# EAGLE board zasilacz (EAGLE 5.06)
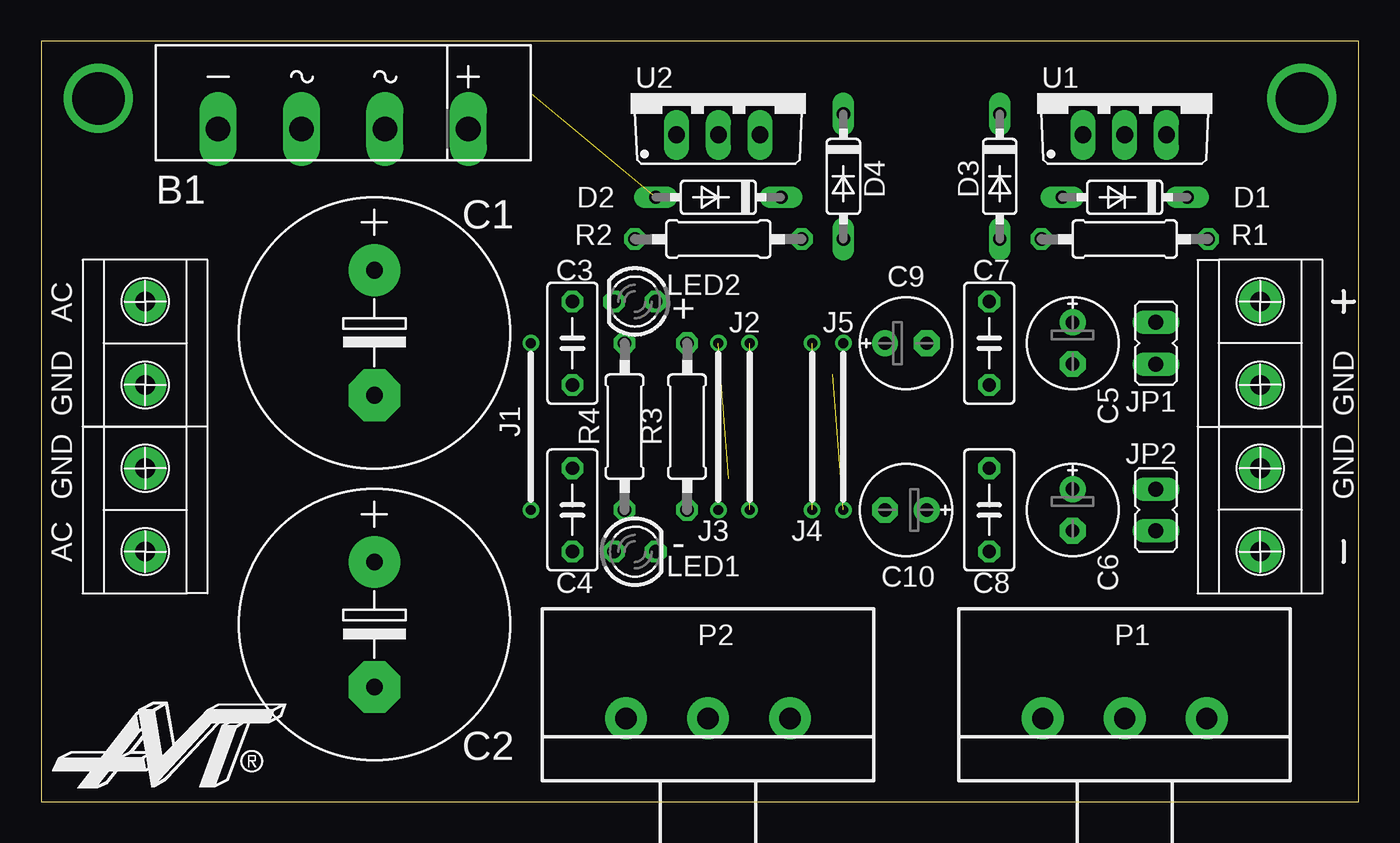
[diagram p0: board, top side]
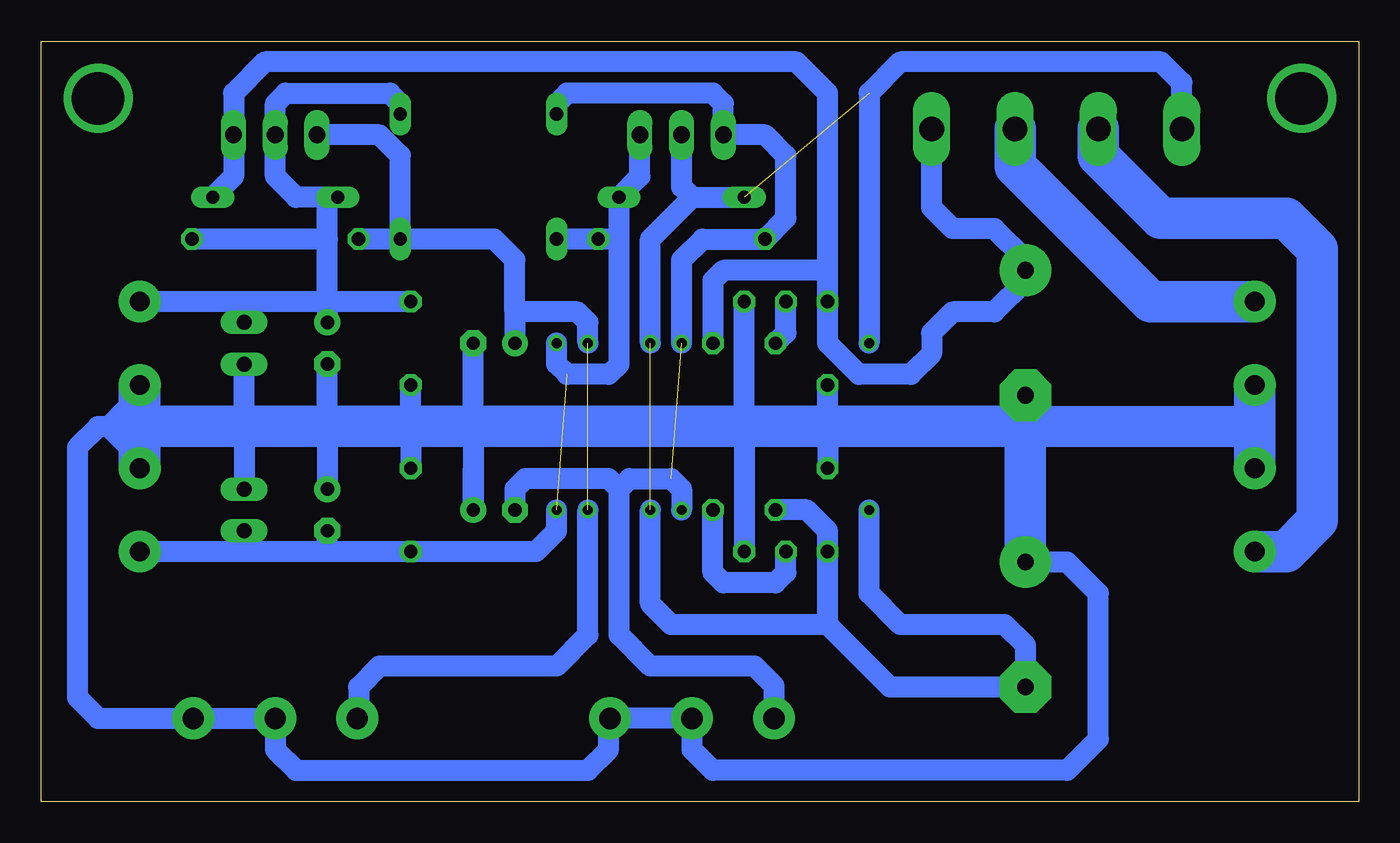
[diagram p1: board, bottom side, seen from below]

Size 80.32 x 46.34 mm. Coordinates in mm from the lower left corner, seen from the top.
Outline: 0,0 80.32,0 80.32,46.34 0,46.34 0,0
Copper layers (1*16): Top 0.035mm / dielectric 1.5mm / Bottom 0.035mm
Design rules "default": minimum track width 10mil, minimum drill 24mil, track to track 8mil, track to pad 8mil, pad to pad 8mil, via to via 8mil, smd to smd 8mil, copper to edge 40mil, drill to drill 8mil, minimum pad ring 10mil, minimum via ring 8mil, stop-mask expansion 4mil, vias tented up to drill 0mil, thermal gap 10mil

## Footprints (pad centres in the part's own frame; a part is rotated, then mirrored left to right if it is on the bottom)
FBU4 = drill 1.499 long: + 7.62,-1.54; - -7.62,-1.54; AC1 2.54,-1.54; AC2 -2.54,-1.54
E7,5-16 = drill 1.016 pad 3.15 round: + -3.81,0 | drill 1.016 pad 3.15 octagon: - 3.81,0
C050-030X075 = drill 0.813 octagon: 1 -2.54,0; 2 2.54,0
E2,5-6E = drill 0.813 pad 1.575 round: + -1.27,0 | drill 0.813 pad 1.575 octagon: - 1.27,0
DO35-7 = drill 0.813 long: A 3.81,0; C -3.81,0
JP1 = drill 0.914 long: 1 0,-1.27; 2 0,1.27
LED3MM = drill 0.813 octagon: A -1.27,0; K 1.27,0
CIP20C-4MM = drill 1.3 pad 2.54 round: A -5,0; E 5,0; S 0,0
0207/10 = drill 0.813 octagon: 1 -5.08,0; 2 5.08,0
TO220BV = drill 1.016 long: D 0,-2.54; G -2.54,-2.54; S 2.54,-2.54
ARK2 = drill 1.2 pad 2.54 round: 1 -2.54,0; 3 2.54,0 | drill 0.8 pad 2.54 round: 2 2.54,0

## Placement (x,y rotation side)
B1  RECTIFIER-FBU4  [FBU4]  18.42,42.55 0 top
C1  [E7,5-16]  20.32,28.58 270 top
C2  [E7,5-16]  20.32,10.79 270 top
C3  [C050-030X075]  32.38,27.94 270 top
C4  [C050-030X075]  32.38,17.78 270 top
C5  [E2,5-6E]  62.86,27.94 270 top
C6  [E2,5-6E]  62.86,17.78 270 top
C7  [C050-030X075]  57.78,27.94 270 top
C8  [C050-030X075]  57.78,17.78 270 top
C9  [E2,5-6E]  52.7,27.94 0 top
C10  [E2,5-6E]  52.7,17.78 180 top
D1  1N4007  [DO35-7]  66.04,36.83 180 top
D2  1N4007  [DO35-7]  41.27,36.83 180 top
D3  1N4007  [DO35-7]  58.42,38.1 270 top
D4  1N4007  [DO35-7]  48.89,38.1 270 top
JP1  [JP1]  67.95,27.94 0 top
JP2  [JP1]  67.95,17.78 0 top
LED1  [LED3MM]  36.2,15.24 0 top
LED2  [LED3MM]  36.2,30.48 180 top
P1  [CIP20C-4MM]  66.04,5.08 0 top
P2  [CIP20C-4MM]  40.64,5.08 0 top
R1  [0207/10]  66.04,34.29 0 top
R2  [0207/10]  41.27,34.29 180 top
R3  [0207/10]  39.37,22.86 90 top
R4  [0207/10]  35.56,22.86 90 top
U1  LM317  [TO220BV]  66.04,43.18 0 top
U2  LM337  [TO220BV]  41.27,43.18 0 top
U$1  ARK2  [ARK2]  6.35,27.94 270 top
U$2  ARK2  [ARK2]  6.35,17.78 270 top
U$3  ARK2  [ARK2]  74.3,27.94 90 top
U$4  ARK2  [ARK2]  74.3,17.78 90 top

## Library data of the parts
B1 = rectifier
C1-C10 R1-R4 = rcl
D1-D4 = diode
JP1 JP2 = jumper
LED1 LED2 = led
P1 P2 = pot2
U1 U2 = transistor-power
U$1-U$4 = ark2

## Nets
N$1: B1.AC1 U$1.1
N$2: B1.AC2 U$2.2
N$4: B1.- C2.- C4.2 D2.A R4.1 U2.D
N$5: C5.+ C7.1 D1.A D3.C JP1.2 R1.2 U1.D U$3.2
N$6: C6.- C8.2 D2.C D4.A JP2.1 R2.1 U2.S U$4.1
N$7: C9.+ D3.A P1.A R1.1 U1.G
N$8: C10.- D4.C P2.A R2.2 U2.G
N$9: LED1.A R3.1
N$10: LED2.K R4.2
N$11: C1.- C2.+ C3.2 C4.1 C5.- C6.+ C7.2 C8.1 C9.- C10.+ JP1.1 JP2.2 LED1.K LED2.A P1.E P1.S P2.E P2.S U$1.2 U$2.1 U$3.1 U$4.2
N$14: B1.+ C1.+ C3.1 D1.C R3.2 U1.S

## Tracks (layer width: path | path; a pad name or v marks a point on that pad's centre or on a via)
N$1
  Bottom 2.54: U$1.1 12.7,30.48 20.96,38.73 B1.AC1
N$2
  Bottom 2.54: B1.AC2 15.88,39.37 12.06,35.56 4.45,35.56 2.54,33.66 2.54,17.14 4.45,15.24 U$2.2
N$4  (via drill 0.6)  (2 unrouted)
  Bottom 1.27: 40.64,36.83 D2.A | 40.64,36.83 41.27,37.46 U2.D | 32.38,10.79 28.58,6.98 C2.- 20.32,9.52 21.59,10.79 27.94,10.79 29.85,12.7 v29.85,17.78 | 32.38,10.79 C4.2 32.38,16.51 33.66,17.78 R4.1 | 40.64,36.83 43.18,34.29 v43.18,27.94 | v43.18,17.78 43.18,12.06 41.91,10.79 32.38,10.79 | v29.85,27.94 29.85,43.18 27.94,45.09 12.06,45.09 10.79,43.81 B1.-
N$5
  Bottom 1.27: D3.C 58.42,42.55 59.05,43.18 65.41,43.18 66.04,42.55 U1.D 66.04,38.1 64.77,36.83 62.86,36.83 | 62.86,36.83 D1.A | 62.86,30.48 67.95,30.48 | 67.95,30.48 U$3.2 | C7.1 62.86,30.48 | 62.86,30.48 62.86,34.29 | 62.86,34.29 62.86,36.83 | 67.95,30.48 JP1.2 | 62.86,34.29 R1.2 | 62.86,30.48 C5.+
N$6  (via drill 0.6)  (1 unrouted)
  Bottom 1.27: U2.S 43.81,38.1 D2.C 45.09,34.29 | 62.86,15.24 C8.2 50.16,15.24 48.89,16.51 v48.89,17.78 | 62.86,15.24 67.95,15.24 | 67.95,15.24 U$4.1 | v48.89,27.94 48.89,26.67 48.26,26.03 45.72,26.03 45.09,26.67 45.09,34.29 | 45.09,34.29 R2.1 D4.A | 67.95,15.24 JP2.1 | 62.86,15.24 C6.-
N$7  (via drill 0.6)  (1 unrouted)
  Bottom 1.27: D3.A R1.1 | D3.A 58.42,39.37 59.69,40.64 U1.G | D3.A 52.7,34.29 51.43,33.02 51.43,29.84 | v46.99,27.94 46.99,29.21 47.62,29.84 51.43,29.84 | 51.43,29.84 C9.+ | v46.99,17.78 46.99,10.16 48.89,8.25 59.69,8.25 60.96,6.98 60.96,5.16 P1.A
N$8  (via drill 0.6)  (1 unrouted)
  Bottom 1.27: D4.C 48.89,42.55 48.26,43.18 39.37,43.18 38.73,42.55 U2.G 36.2,40.64 34.92,39.37 34.92,35.56 R2.2 40,34.29 41.27,33.02 v41.27,27.94 | P2.A 35.64,7.06 36.83,8.25 43.18,8.25 45.09,10.16 45.09,19.05 | 45.09,19.05 44.45,19.68 41.91,19.68 41.27,19.05 v41.27,17.78 | 45.09,19.05 45.72,19.68 50.8,19.68 51.43,19.05 C10.-
N$9
  Bottom 1.27: R3.1 39.37,13.97 38.73,13.34 35.56,13.34 34.92,13.97 LED1.A
N$10
  Bottom 1.27: R4.2 34.92,28.58 LED2.K
N$11
  Bottom 1.27: 45.72,5.08 45.72,3.17 46.99,1.9 64.77,1.9 66.04,3.17 P1.S | 74.3,22.22 74.3,22.86 | 74.3,23.49 74.3,22.86 | 57.78,22.86 C8.1 | 57.78,22.86 C7.2 | 6.35,22.86 6.35,22.22 | C2.+ 19.69,14.61 19.69,22.86 | 19.69,22.86 C1.- | 6.35,22.86 6.35,23.49 | 20.32,22.86 6.35,22.86 | 32.38,22.86 C4.1 | 32.38,22.86 C3.2 | 20.32,22.86 19.69,22.86 | 20.32,22.86 32.38,22.86 | 68.58,22.86 74.3,22.86 | 68.58,22.86 67.31,22.86 | 57.78,22.86 62.86,22.86 | 67.31,22.86 62.86,22.86 | 74.3,22.86 75.57,22.86 | 75.57,22.86 76.2,22.86 | 76.2,22.86 76.84,22.86 78.11,21.59 78.11,6.35 76.84,5.08 P1.E | 53.98,22.86 57.78,22.86 | 53.98,22.86 C10.+ 53.98,20.32 | 32.38,22.86 37.46,22.86 | 37.46,22.86 LED2.A | P2.E P2.S 40.64,3.17 39.37,1.9 17.78,1.9 15.88,3.81 15.88,12.7 17.78,14.61 C2.+ | P1.E P1.S | P1.E P1.S | 37.46,22.86 LED1.K | 37.46,22.86 53.98,22.86 | 53.98,22.86 C9.- | 6.35,22.22 U$2.1 5.71,20.32 5.71,25.4 6.98,25.4 6.98,20.32 | 6.35,22.22 67.95,22.22 | 67.95,22.22 74.3,22.22 | 74.3,22.22 U$4.2 73.66,20.32 | 74.3,22.22 74.3,23.49 | 74.3,23.49 U$3.1 | 20.96,23.49 62.86,23.49 | 62.86,23.49 67.95,23.49 | 67.95,23.49 74.3,23.49 | 6.35,23.49 U$1.2 | C2.+ 20.32,22.86 | C2.+ 20.96,14.61 20.96,23.49 | 20.96,23.49 6.35,23.49 | 74.3,23.49 74.93,23.49 75.57,22.86 | 75.57,22.86 74.93,22.22 74.3,22.22 | 73.66,20.32 73.66,25.4 74.93,25.4 74.93,24.13 | 74.93,20.32 74.93,24.13 | 73.66,20.32 74.93,20.32 | 74.93,20.32 74.93,21.59 76.2,22.86 | 76.2,22.86 74.93,24.13 | 67.95,23.49 JP1.1 | 67.95,23.49 67.31,22.86 | 67.95,22.22 JP2.2 | 67.95,22.22 68.58,22.86 | 62.86,23.49 C5.- | 62.86,22.86 C6.+
N$12  (via drill 3.2)
  other vias: 76.84,42.86
N$13  (via drill 3.2)
  other vias: 3.49,42.86
N$14
  Bottom 1.27: D1.C 68.58,38.1 U1.S 68.58,43.18 66.68,45.09 34.29,45.09 32.38,43.18 32.38,32.38 | R3.2 39.37,31.75 38.73,32.38 32.38,32.38 | 32.38,32.38 C3.1 32.38,27.94 30.48,26.03 27.31,26.03 26.04,27.3 26.04,28.58 24.77,29.84 22.23,29.84 20.32,31.75 C1.+ 20.32,33.02 22.23,34.92 24.77,34.92 26.04,36.2 B1.+

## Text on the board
tPlace: AC | + | J2 | J5 | GND | GND | J1 | GND | GND | J3 | J4 | - | AC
